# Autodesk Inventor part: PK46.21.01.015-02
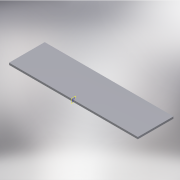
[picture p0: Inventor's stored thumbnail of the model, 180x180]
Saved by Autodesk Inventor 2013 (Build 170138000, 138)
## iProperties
Created: 2005-04
Part Number: PK46.21.01.015-02
Material: Steel, Mild
Document SubType Name: Modeling
Designer: salex
Manufacturer: Standard
Standards Organization: Custom
Density: 7.86 g/cm^3
Author: salex
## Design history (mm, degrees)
sketch "Эскиз1"
  geometry: L1 (0, 0)-(650, 0); L2 (650, 0)-(650, 180); L3 (650, 180)-(0, 180); L4 (0, 180)-(0, 0)
  constraints: 8 end point, 2 parallel, 1 horizontal, 1 perpendicular, 1 other
  dimensions: "d0" = 180 distance of L3.end L1.start; "d1" = 650 distance of L1.start L1.end
extrude "Выдавливание1" new body sketch "Эскиз1" distance "d2" = 10; taper "d3" = 0 deg
node "РабПлоскость1"
body "Solid1"
